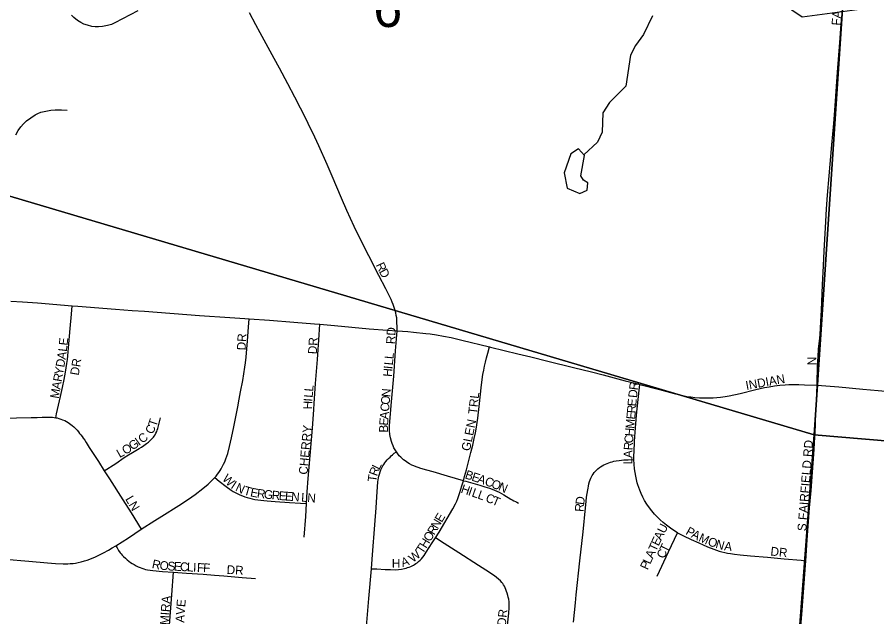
# Model space of a CAD drawing. Extents: x 1410790 to 1770854, y 448063 to 770588.
# Drawn here: x 1523216 to 1528108, y 619468 to 622880 of the extents above; entities that cross this region are included whole.
import ezdxf

# ---------------------------------------------------------------- set-up
doc = ezdxf.new("R2010")
doc.units = 0
for name, color, linetype in [('GM_X_City_Street', 7, 'Continuous'), ('GM_X_City_Street_Text', 7, 'Continuous'), ('GM_X_Minor_Lake', 7, 'Continuous'), ('GM_X_Minor_River', 7, 'Continuous'), ('GM_X_Section', 7, 'Continuous'), ('GM_X_Section_Text', 7, 'Continuous')]:
    doc.layers.add(name, color=color, linetype=linetype)

msp = doc.modelspace()

# ---------------------------------------------------------------- linework, layer by layer
at = {"layer": 'GM_X_City_Street'}
for points in [[(1527791.3, 621181.8), (1527793.1, 621212), (1527799.6, 621357.4), (1527804, 621464.9), (1527808.7, 621550.1), (1527815.7, 621681.1), (1527821.3, 621788.8), (1527826.5, 621867), (1527836.3, 621978.2), (1527852.7, 622154), (1527862.8, 622274.8), (1527868.3, 622350), (1527885.1, 622567.1), (1527897.2, 622735.6), (1527905.6, 622840.2), (1527915.8, 622957.8), (1527927.1, 623088.4), (1527939, 623232.3), (1527940.7, 623251.7)], [(1523902.7, 622916.6), (1523772.6, 622847.7), (1523752, 622839), (1523730.4, 622832.7), (1523701.9, 622827.5), (1523679.5, 622825.3), (1523660.4, 622825.5), (1523641.5, 622827.8), (1523616.5, 622834), (1523595.3, 622841.3), (1523578.2, 622849.7), (1523559.3, 622861.9), (1523538.9, 622877.7), (1523525.1, 622890.9)], [(1525379, 621095.1), (1525378.3, 621116), (1525377.5, 621144.7), (1525377.1, 621156.9), (1525375.8, 621169), (1525373.6, 621182.9), (1525370.1, 621198.1), (1525366.6, 621211.1), (1525362.7, 621223.3), (1525359.3, 621234.6), (1525355.3, 621245.4), (1525350.2, 621259.3), (1525344.1, 621273.2), (1525313.7, 621334.4), (1525274.2, 621409.9), (1525216.8, 621522.8), (1525184.8, 621585.7), (1525133.1, 621690), (1525091.5, 621779.3), (1525061.1, 621850.9), (1525008.1, 621975.4), (1524979.5, 622042.3), (1524932.6, 622147.7), (1524909.6, 622197.2), (1524871.8, 622275.7), (1524848.6, 622323.1), (1524828.4, 622363), (1524796.3, 622425.5), (1524756.4, 622500.2), (1524709, 622589.5), (1524679.4, 622644.4), (1524655.8, 622687.5), (1524598.8, 622790.9), (1524574.5, 622837.4), (1524538.1, 622905.5)], [(1523208.4, 622211.7), (1523221.8, 622234.9), (1523237.3, 622256.6), (1523252.8, 622274.3), (1523270, 622290.2), (1523293.9, 622308.2), (1523319, 622324.4), (1523334, 622332.3), (1523351.6, 622339), (1523369.1, 622343.8), (1523388.5, 622348), (1523408.3, 622351.4), (1523431.6, 622353.2), (1523449.2, 622353.9), (1523468, 622353.3), (1523501, 622351.2)], [(1523180.1, 621264.8), (1523246.7, 621261), (1523331.8, 621254.4), (1523529.2, 621237.9)], [(1523435.6, 620601), (1523440.4, 620622.5), (1523462.6, 620721.9), (1523473.8, 620773.3), (1523483.2, 620818.1), (1523491.5, 620860.4), (1523495.8, 620884.9), (1523499.5, 620909.2), (1523502.3, 620931.4), (1523504.5, 620952.2), (1523509.1, 620997.7), (1523518.1, 621109.2), (1523525.1, 621191), (1523529.2, 621237.9)], [(1523529.2, 621237.9), (1523560.6, 621235.3), (1523776.4, 621219.2), (1523871.2, 621211.7), (1523939.9, 621206.5), (1524253.8, 621183.2), (1524427.1, 621170.9), (1524512.2, 621165), (1524535.7, 621163.4)], [(1524340.5, 620260.3), (1524347.8, 620268.7), (1524356.3, 620279.6), (1524364.1, 620289.8), (1524370.4, 620299.6), (1524376.6, 620309.6), (1524383.4, 620322.3), (1524390.2, 620336.2), (1524396.9, 620350.3), (1524403.4, 620366.7), (1524408.6, 620381.3), (1524414.1, 620398), (1524424.5, 620436.3), (1524436, 620487), (1524449.4, 620548.2), (1524459.3, 620596), (1524471.5, 620662.9), (1524479.5, 620707.3), (1524487.8, 620748.8), (1524500.1, 620813.2), (1524506.7, 620851.4), (1524512.5, 620887.8), (1524515.4, 620912.5), (1524518.9, 620945.5), (1524527.1, 621038), (1524532.5, 621116.6), (1524535.7, 621163.4)], [(1524535.7, 621163.4), (1524652.9, 621155.5), (1524790.4, 621145.5), (1524908.1, 621135.7), (1524939, 621132.9)], [(1527769, 620786.5), (1527771.2, 620901.6), (1527773.4, 620948.3), (1527776.7, 620992), (1527781, 621035.8), (1527784.9, 621073.6), (1527791.3, 621181.8)], [(1524863.3, 620112.7), (1524866.9, 620179.4), (1524872.3, 620254.4), (1524877.6, 620319.2), (1524895.8, 620541.2), (1524902.2, 620619.3), (1524904.1, 620648.1), (1524905.9, 620682.7), (1524913.9, 620795.3), (1524925.2, 620932.3), (1524934.9, 621072.9), (1524939, 621132.9)], [(1524939, 621132.9), (1525022.5, 621125.4), (1525219.2, 621107), (1525323.9, 621098.9), (1525379, 621095.1)], [(1525373.9, 620407.6), (1525367, 620418.6), (1525360.4, 620430.3), (1525355.5, 620440.4), (1525350.3, 620453.7), (1525346.2, 620465.7), (1525340.1, 620487.3), (1525336.7, 620506.1), (1525335.1, 620528.5), (1525335, 620542.6), (1525335.8, 620557.5), (1525346.2, 620691.5), (1525359.1, 620837.6), (1525368.2, 620981.2), (1525379, 621095.1)], [(1525379, 621095.1), (1525440, 621090.9), (1525471.6, 621088.3), (1525541.9, 621081), (1525565.9, 621078.2), (1525601.7, 621073), (1525642.3, 621065.9), (1525685.2, 621056.5), (1525746.1, 621041.4), (1525904.6, 621003.8)], [(1525755.2, 620242.6), (1525762, 620266.2), (1525772.5, 620304.1), (1525798.1, 620402.6), (1525808.7, 620445), (1525817.3, 620482.4), (1525823.5, 620514.4), (1525829.6, 620546.9), (1525833.9, 620573.5), (1525837.4, 620598.8), (1525844.6, 620663.9), (1525857.8, 620787.9), (1525866.6, 620846.3), (1525870.8, 620872), (1525875, 620893.5), (1525881.1, 620917.9), (1525887.3, 620942.4), (1525894.4, 620967.6), (1525904.6, 621003.8)], [(1525904.6, 621003.8), (1525910, 621002.5), (1526065.9, 620964.5), (1526139.8, 620946.7), (1526235.3, 620922.8), (1526381.8, 620886.2), (1526483.8, 620861.1), (1526550.7, 620844), (1526676.8, 620811.7), (1526733.4, 620797.1), (1526758.9, 620790.3)], [(1526726.2, 620364), (1526726.1, 620385.4), (1526726.8, 620407), (1526730, 620466.2), (1526733.1, 620517.9), (1526741, 620615.2), (1526755.6, 620758.6), (1526758.9, 620790.3)], [(1526758.9, 620790.3), (1526871.1, 620760.7), (1526954.6, 620738.6), (1527004.6, 620726.9), (1527027, 620722.3), (1527049.2, 620719), (1527072.3, 620716.1), (1527099.6, 620714.2), (1527137.5, 620713.2), (1527176.5, 620713.9), (1527198.2, 620715.2), (1527218.8, 620717.2), (1527245.6, 620721.1), (1527266.9, 620724.9), (1527330.6, 620739.5), (1527419.9, 620761.8), (1527468.3, 620771.9), (1527495.6, 620777.2), (1527526.3, 620782), (1527557, 620785.7), (1527586, 620787.8), (1527607.9, 620789), (1527634.3, 620789.5), (1527665, 620789), (1527696.1, 620788.1), (1527769, 620786.5)], [(1527703.9, 619787), (1527712.4, 619905.2), (1527725.7, 620088.1), (1527733.8, 620186.1), (1527741.6, 620290.6), (1527747.2, 620367.3), (1527750.7, 620421.7), (1527755.6, 620490.3), (1527759.6, 620555.9), (1527761.6, 620643.9), (1527765, 620698.1), (1527769, 620786.5)], [(1527769, 620786.5), (1527891, 620777), (1528028.3, 620763.8), (1528116.4, 620755.2), (1528367.9, 620732.6), (1528652.3, 620707.5), (1528802.6, 620693.4), (1528926.5, 620682.1), (1529092.9, 620667.4), (1529174.6, 620659.2), (1529223.7, 620653), (1529246.8, 620649.2), (1529272.6, 620643.8), (1529299.7, 620636.9), (1529318.5, 620631.2), (1529340.7, 620623.7), (1529379.6, 620607), (1529415.4, 620589.2), (1529455.6, 620565.8), (1529480.5, 620549.3), (1529513, 620526.2), (1529586.1, 620470.5), (1529590.5, 620467.5)], [(1522432.1, 620598.7), (1522455.5, 620596.7), (1522569.6, 620587.1), (1522625.2, 620582.6), (1522641.5, 620581.3), (1522673.7, 620579.9), (1522752.2, 620579.9), (1522801.4, 620580.7), (1522893.1, 620585.4), (1522935.6, 620587.4), (1523017.3, 620591.3), (1523072.8, 620594.3), (1523134.5, 620596.4), (1523213, 620599.6), (1523295.2, 620601.4), (1523330.2, 620602.6), (1523358.4, 620604), (1523376.7, 620604.8), (1523393.6, 620604.5), (1523409.1, 620603.8), (1523417.3, 620603.4), (1523426.6, 620602.3), (1523435.6, 620601)], [(1523435.6, 620601), (1523444.4, 620599.3), (1523453.3, 620597.2), (1523464.3, 620593.4), (1523474.4, 620589.5), (1523486.5, 620584.1), (1523497.6, 620578.4), (1523506, 620573.9), (1523513.9, 620568.4), (1523521.4, 620563.1), (1523529.2, 620556.8), (1523538.8, 620548.5), (1523548.1, 620539.3), (1523556.6, 620530.1), (1523565.2, 620520.1), (1523571.6, 620512), (1523578.3, 620503.1), (1523585.4, 620493.8), (1523592.5, 620483.6), (1523600.2, 620472.8), (1523608.7, 620460.1), (1523626.6, 620431.7), (1523678.3, 620352), (1523711.5, 620297.7)], [(1523711.5, 620297.7), (1523776.8, 620341), (1523825.6, 620374.4), (1523849.2, 620389), (1523873.1, 620403.6), (1523910.3, 620424.8), (1523924.1, 620433.5), (1523937.8, 620442.8), (1523951.6, 620453.2), (1523964, 620462.6), (1523973.1, 620470.3), (1523981.1, 620478), (1523986.8, 620483.8), (1523992, 620490.4), (1523996.6, 620496.6), (1524001.2, 620504), (1524005.7, 620512.4), (1524010, 620521.6), (1524013.7, 620530.7), (1524016.9, 620540), (1524026.9, 620578), (1524032.5, 620600.4)], [(1525232.3, 619741.6), (1525232.3, 619742), (1525238, 619820.6), (1525251.1, 619990.7), (1525258.2, 620088.9), (1525262.5, 620151), (1525269.3, 620235.9), (1525270.8, 620247), (1525272.4, 620258.2), (1525274.7, 620268.9), (1525277.8, 620280), (1525282.1, 620292.5), (1525286.4, 620304.2), (1525291.8, 620316.2), (1525297.7, 620327.2), (1525302.2, 620334.8), (1525308, 620343.4), (1525314.8, 620352.2), (1525322.2, 620360.8), (1525330, 620369.4), (1525337.9, 620377.1), (1525344.6, 620383.5), (1525352.2, 620390.2), (1525362.2, 620398.3), (1525373.9, 620407.6)], [(1525755.2, 620242.6), (1525664.5, 620268.9), (1525582.8, 620292.7), (1525546.9, 620302.6), (1525513.5, 620312.3), (1525498.5, 620316.9), (1525485.8, 620321.3), (1525473.1, 620326.3), (1525462.1, 620331.3), (1525449.4, 620338), (1525439.7, 620343.8), (1525431.7, 620349.1), (1525423.9, 620354.6), (1525414.9, 620361.8), (1525406.6, 620369), (1525398.5, 620377), (1525390.8, 620384.8), (1525381.9, 620395.7), (1525373.9, 620407.6)], [(1526382, 619437.4), (1526392.5, 619548), (1526396.6, 619593.6), (1526417.1, 619785.7), (1526425.5, 619853.4), (1526434.6, 619934.1), (1526440.8, 619988.7), (1526446.4, 620050.6), (1526453.8, 620124.7), (1526456.9, 620147.9), (1526460.1, 620169.9), (1526463.4, 620190.1), (1526465.3, 620200.6), (1526467.3, 620212.2), (1526470, 620224.9), (1526473.6, 620238.2), (1526476.5, 620247.4), (1526480.3, 620257.3), (1526483.9, 620264.6), (1526488.3, 620272.4), (1526493.5, 620280.2), (1526500.2, 620289), (1526506.3, 620296.1), (1526514, 620303.8), (1526521, 620310.4), (1526529.3, 620317.1), (1526536, 620321.5), (1526544.5, 620326.5), (1526555.1, 620332.1), (1526564, 620336.3), (1526573.8, 620340.7), (1526582.6, 620344.1), (1526592.6, 620347.6), (1526602.2, 620350.3), (1526612.1, 620352.7), (1526625.6, 620355.1), (1526641.7, 620357.3), (1526668.8, 620360.3), (1526693.3, 620362), (1526726.2, 620364)], [(1526974.3, 619945.9), (1526953.2, 619958.7), (1526933.1, 619972.6), (1526910.9, 619989.9), (1526892.8, 620004.1), (1526875, 620019.5), (1526857.9, 620036.3), (1526843.5, 620052), (1526820.8, 620079.6), (1526800, 620108.6), (1526786.4, 620130.4), (1526776.9, 620148.9), (1526767.1, 620168.9), (1526759.3, 620187.9), (1526753.6, 620203.1), (1526748.5, 620218.2), (1526744.8, 620230.7), (1526740.5, 620248.5), (1526736.4, 620268.6), (1526732.9, 620288.3), (1526729.5, 620310.3), (1526727.2, 620335.8), (1526726.2, 620364)], [(1523711.5, 620297.7), (1523740.6, 620252.3), (1523816.6, 620134), (1523863.9, 620059.3), (1523922.3, 619965.8)], [(1523922.3, 619965.8), (1524000.3, 620015.8), (1524039.2, 620040.1), (1524136.5, 620101.4), (1524190.8, 620138.1), (1524228.6, 620164.5), (1524273.4, 620198.1), (1524303.8, 620223.6), (1524327.8, 620246.6), (1524340.5, 620260.3)], [(1524340.5, 620260.3), (1524365.7, 620240.2), (1524404.5, 620209.9), (1524434, 620188.8), (1524445.6, 620181.5), (1524456.9, 620175.1), (1524471, 620167.8), (1524483.7, 620162), (1524497.6, 620156.5), (1524511.6, 620151.4), (1524525.1, 620147), (1524540.2, 620142.9), (1524553.8, 620139.3), (1524569.3, 620136.3), (1524585.1, 620133.9), (1524602.1, 620132), (1524620.4, 620130), (1524639.5, 620128.4), (1524661, 620126.5), (1524684.7, 620124.9), (1524765.5, 620118.9), (1524827.7, 620115), (1524863.3, 620112.7)], [(1525596.1, 619917.4), (1525616.6, 619949.2), (1525696.2, 620081.4), (1525711, 620110.6), (1525717.9, 620126.1), (1525723.8, 620140.8), (1525729.9, 620157.4), (1525735.5, 620174.8), (1525746.5, 620212.6), (1525755.2, 620242.6)], [(1525755.2, 620242.6), (1525768.7, 620238.9), (1525848.1, 620216.6), (1525877.2, 620208), (1525904.8, 620199.3), (1525919.5, 620194.3), (1525932.9, 620189.3), (1525946.2, 620183.5), (1525959.8, 620176.7), (1525972.4, 620170), (1525985.9, 620162.3), (1526024.5, 620137.5), (1526033, 620132.7), (1526041.5, 620128.4), (1526051.4, 620123.6), (1526060.3, 620119.4), (1526069.7, 620115.5)], [(1524849.5, 619921.6), (1524858.9, 620038.8), (1524863.3, 620112.7)], [(1523777.7, 619871.6), (1523848.9, 619917.7), (1523922.3, 619965.8)], [(1526858.1, 619698.2), (1526922.1, 619836.7), (1526974.3, 619945.9)], [(1526974.3, 619945.9), (1527008.3, 619928.7), (1527051.6, 619908.5), (1527095.9, 619888), (1527144.7, 619866.8), (1527180.9, 619852.4), (1527211.5, 619841.8), (1527226.7, 619837.2), (1527242.9, 619833.4), (1527258.3, 619830.1), (1527274.8, 619827.3), (1527299, 619823.6), (1527329.7, 619820.1), (1527389.5, 619814.4), (1527486.9, 619806.8), (1527581, 619798.1), (1527677.4, 619789.4), (1527703.9, 619787)], [(1525232.3, 619741.6), (1525262, 619740.4), (1525310.6, 619738), (1525341.1, 619736.6), (1525367.5, 619736.1), (1525386.6, 619737.1), (1525402.9, 619739.3), (1525419.5, 619742.7), (1525428.8, 619745.3), (1525438, 619748.3), (1525446.4, 619750.9), (1525456.4, 619754.8), (1525463.2, 619757.6), (1525471.3, 619761.7), (1525477.9, 619765.9), (1525485.1, 619770.5), (1525492.7, 619775.8), (1525500.7, 619782.6), (1525508.7, 619789.9), (1525517.1, 619798.7), (1525524.1, 619807.3), (1525531.4, 619816.8), (1525544.5, 619835.6), (1525577.5, 619888.5), (1525596.1, 619917.4)], [(1525994.4, 619316.3), (1526013.2, 619489), (1526015.8, 619518.5), (1526016.4, 619527.7), (1526016, 619538.1), (1526015.2, 619552.8), (1526013.2, 619567.5), (1526010.9, 619579.4), (1526008.5, 619589.9), (1526005.1, 619602.2), (1526001.5, 619612.6), (1525997.2, 619623.4), (1525992.8, 619633.1), (1525988.5, 619641.9), (1525983.3, 619650.4), (1525979, 619656.9), (1525973.8, 619663.7), (1525965.7, 619672.5), (1525955.1, 619682.1), (1525944.4, 619690.9), (1525932, 619700.4), (1525883.6, 619734.1), (1525842.2, 619760.6), (1525728.8, 619832.8), (1525645.7, 619885.2), (1525596.1, 619917.4)], [(1523147.5, 619795.4), (1523281.6, 619785.2), (1523389.3, 619775.1), (1523434, 619772), (1523477.9, 619769.5), (1523491.5, 619769.2), (1523504.4, 619769.4), (1523518.6, 619770.3), (1523534.3, 619772), (1523547.9, 619774), (1523563.7, 619777), (1523580.9, 619781.1), (1523599.1, 619785.9), (1523614.8, 619790.5), (1523629.8, 619795.4), (1523643.6, 619801.3), (1523658.1, 619807.7), (1523681.2, 619818.4), (1523708.3, 619832.7), (1523735.2, 619847), (1523756.9, 619859.5), (1523777.7, 619871.6)], [(1523777.7, 619871.6), (1523781.2, 619865.4), (1523784.5, 619859.5), (1523788.8, 619851.9), (1523793.6, 619844.6), (1523802.3, 619832.8), (1523808, 619825.9), (1523814.2, 619819.4), (1523822.1, 619810.4), (1523832, 619800.8), (1523841.2, 619792.7), (1523851.7, 619784.3), (1523861, 619777.7), (1523870.1, 619771.4), (1523881, 619764.9), (1523892.4, 619758.6), (1523904, 619752.9), (1523915.8, 619747.8), (1523925.9, 619743.8), (1523936.9, 619740.2), (1523947.1, 619737.5), (1523958.7, 619735.1), (1523972.8, 619733), (1523987.5, 619731.1), (1524042.7, 619726.3), (1524105.3, 619721.1)], [(1525142.1, 618661.5), (1525147.9, 618731.8), (1525159.3, 618869.2), (1525173, 619042.5), (1525185.1, 619179.9), (1525196.2, 619317.2), (1525202.4, 619389.1), (1525217.3, 619572.2), (1525232.3, 619741.6)], [(1527669.6, 619344.3), (1527682.8, 619505.5), (1527702, 619761.3), (1527703.9, 619787)], [(1524078.3, 619332.6), (1524083.5, 619420.2), (1524096.7, 619592.5), (1524105.3, 619721.1)], [(1524105.3, 619721.1), (1524106, 619721.1), (1524179.9, 619716.6), (1524274.6, 619710.2), (1524339.9, 619705.5), (1524392.2, 619701.5), (1524497.3, 619692.1), (1524571.6, 619686.7)]]:
    msp.add_lwpolyline(points, dxfattribs=at)
at = {"layer": 'GM_X_Minor_Lake'}
for points in [[(1526444.3, 622092.7), (1526411, 622131.5), (1526366.4, 622102.4), (1526328.3, 621994.9), (1526346.6, 621908.2), (1526418.1, 621876.5), (1526460.6, 621895.6), (1526463.4, 621937.7), (1526439.6, 621952.3), (1526424, 621976.7)], [(1526424, 621976.7), (1526444.3, 622092.7)]]:
    msp.add_lwpolyline(points, dxfattribs=at)
at = {"layer": 'GM_X_Minor_River'}
for points in [[(1527996.4, 622921.4), (1527683.1, 622880.1), (1527566.5, 622960.9)], [(1526832, 622888.8), (1526779.9, 622781.6), (1526734.7, 622718.3), (1526705.6, 622664.8), (1526680.1, 622486.8), (1526586.3, 622394.5), (1526549.1, 622335.2), (1526545, 622226.9)], [(1526545, 622226.9), (1526517.9, 622169.3), (1526439.9, 622097.7)]]:
    msp.add_lwpolyline(points, dxfattribs=at)
at = {"layer": 'GM_X_Section'}
for points in [[(1522801.4, 625129.5), (1527484, 624666.3), (1528025, 624614.9), (1527751.7, 620502.8), (1522551.9, 622046.6)], [(1528025, 624614.9), (1532828.2, 624183.7), (1533518.9, 624117.7), (1533190.3, 620044.5), (1527751.7, 620502.8)], [(1527751.7, 620502.8), (1527349.3, 615167.2), (1522119.9, 616619.5), (1522551.9, 622046.6)], [(1533190.3, 620044.5), (1532724.4, 614740.1), (1527349.3, 615167.2), (1527751.7, 620502.8)]]:
    msp.add_lwpolyline(points, close=True, dxfattribs=at)

# ---------------------------------------------------------------- texts
at = {"layer": 'GM_X_City_Street_Text'}
for s, rotation, p in [('FAIRFIELD', 85.169, (1527899.9, 622831.2)), ('R', 295.1856, (1525255.7, 621470.6)), ('D', 297.6797, (1525273.5, 621432.7)), ('RD', 86.8222, (1525365.3, 621018.5)), ('DR', 86.989, (1524516.1, 620983.3)), ('E', 83.6575, (1523502.3, 621010)), ('DR', 86.989, (1524920.9, 620961.3)), ('A', 81.3306, (1523491.3, 620929.4)), ('L', 83.2943, (1523498.1, 620974.7)), ('L', 84.4695, (1525356.8, 620932.7)), ('D', 79.9949, (1523483.4, 620884.8)), ('DR', 81.028, (1523566.3, 620839.2)), ('L', 84.4716, (1525353.5, 620897.6)), ('N', 90, (1527763.5, 620899.2)), ('Y', 79.9806, (1523475.8, 620841.5)), ('H', 85.142, (1525347.6, 620832.1)), ('I', 84.5286, (1525351.4, 620875.8)), ('R', 79.9906, (1523468.9, 620802.5)), ('INDIAN', 10.4039, (1527366.2, 620758.7)), ('A', 79.9844, (1523461.2, 620759.1)), ('L', 85.0888, (1524900, 620748.3)), ('R', 82.167, (1526746.9, 620755.3)), ('M', 79.9867, (1523452, 620707.1)), ('L', 85.4043, (1524897.2, 620713.2)), ('O', 85.3289, (1525335.2, 620673.3)), ('N', 85.336, (1525338.8, 620717.2)), ('TRL', 83.4219, (1525831.7, 620618.6)), ('D', 84.583, (1526742.9, 620712)), ('H', 88.5575, (1524894.5, 620648)), ('I', 85.7773, (1524895.6, 620691.4)), ('C', 85.3433, (1525332, 620633.9)), ('R', 84.9782, (1526735.2, 620624.4)), ('E', 84.993, (1526738.6, 620663.9)), ('A', 85.3725, (1525328.5, 620590)), ('E', 84.98, (1526732.1, 620589.4)), ('T', 71.3776, (1524006.8, 620545.4)), ('E', 86.3504, (1525326.2, 620555.1)), ('GLEN', 78.4074, (1525792.2, 620408.1)), ('M', 84.9853, (1526727.5, 620536.8)), ('C', 63.1462, (1523985.9, 620502.8)), ('CHERRY', 84.8987, (1524868.1, 620275.2)), ('B', 89.15, (1525325.7, 620516.2)), ('H', 84.9768, (1526723.6, 620492.9)), ('G', 35.2931, (1523872.5, 620413.2)), ('I', 36.3272, (1523909.3, 620439.2)), ('C', 36.3308, (1523927, 620452.2)), ('C', 84.9903, (1526720.2, 620453.5)), ('O', 30.42, (1523830.7, 620388.4)), ('R', 85.5994, (1526717.1, 620414.2)), ('S FAIRFIELD RD', 85.6416, (1527706.1, 619953.9)), ('L', 29.4805, (1523799.3, 620370.6)), ('A', 88.6668, (1526716.1, 620370.9)), ('L', 63.6915, (1525276.5, 620301)), ('L', 89.877, (1526716.1, 620335.9)), ('W', 315.7311, (1524379.3, 620249)), ('R', 69.8333, (1525263.4, 620265.1)), ('B', 341.542, (1525760.4, 620256.9)), ('E', 341.5132, (1525798, 620244.4)), ('I', 326.3961, (1524428.1, 620202.7)), ('T', 82.6175, (1525259.6, 620233.1)), ('A', 341.5289, (1525831.4, 620233.2)), ('C', 340.5398, (1525872.9, 620219.3)), ('O', 337.6954, (1525909.6, 620206.4)), ('N', 336.6522, (1525950.1, 620189.8)), ('N', 335.0874, (1524453.7, 620186.5)), ('T', 343.9831, (1524501.5, 620165)), ('E', 348.5988, (1524539.6, 620154.2)), ('R', 353.1411, (1524578.4, 620146.6)), ('G', 353.4975, (1524618.1, 620141.8)), ('R', 354.5886, (1524662.8, 620136.7)), ('E', 355.8162, (1524703.4, 620132.9)), ('H', 341.0328, (1525737, 620175.5)), ('I', 340.9915, (1525778.6, 620161.2)), ('L', 340.7615, (1525799.3, 620154.1)), ('L', 340.2433, (1525832.4, 620142.5)), ('LN', 300.4686, (1523829.6, 620138.3)), ('E', 355.9118, (1524738.6, 620130.3)), ('N', 355.9097, (1524773.7, 620127.8)), ('L', 355.9189, (1524830.8, 620123.7)), ('N', 355.9165, (1524865.9, 620121.2)), ('C', 337.4726, (1525877.3, 620126.2)), ('T', 336.9198, (1525913.8, 620111.1)), ('D', 82.8235, (1526442, 620102.6)), ('R', 85.4299, (1526438.9, 620063.7)), ('E', 59.2035, (1525632.1, 620001.2)), ('R', 59.207, (1525589.3, 619929.4)), ('N', 59.1993, (1525609.5, 619963.4)), ('U', 63.4349, (1526900.5, 619938.4)), ('O', 59.2149, (1525566.7, 619891.6)), ('A', 63.4349, (1526880.8, 619899)), ('P', 331.1802, (1527016.1, 619939.4)), ('A', 332.8682, (1527048.3, 619921.7)), ('M', 335.3936, (1527089.7, 619900.5)), ('H', 59.0815, (1525544.1, 619853.7)), ('T', 65.4501, (1526851.2, 619835.6)), ('E', 64.5226, (1526865.8, 619867.5)), ('T', 64.2659, (1526913.9, 619830.7)), ('O', 340.19, (1527141.9, 619876.8)), ('N', 343.9383, (1527186.7, 619860.8)), ('A', 352.9492, (1527237.4, 619846.9)), ('W', 39.3772, (1525468.2, 619773.9)), ('T', 56.5211, (1525523.3, 619822.3)), ('A', 65.4394, (1526832.9, 619795.6)), ('C', 65.4123, (1526897.6, 619794.9)), ('DR', 353.6511, (1527500.9, 619817.3)), ('R', 347.89, (1523979.9, 619746.1)), ('H', 0.4371, (1525348.4, 619747)), ('A', 18.8583, (1525409.6, 619750.3)), ('L', 65.4501, (1526818.3, 619763.6)), ('O', 354.5803, (1524024.9, 619736.8)), ('S', 356.8605, (1524070.9, 619732.5)), ('E', 357.2005, (1524106.3, 619730.6)), ('C', 357.1819, (1524141.5, 619728.9)), ('L', 357.1827, (1524181, 619726.9)), ('I', 357.1952, (1524216.2, 619725.2)), ('F', 357.1847, (1524238.2, 619724.1)), ('F', 357.1897, (1524273.3, 619722.4)), ('DR', 356.9887, (1524407.2, 619711.7)), ('P', 65.4396, (1526803.7, 619731.6)), ('ALMIRA', 85.8387, (1524071.7, 619337.9)), ('AVE', 86.0531, (1524166.3, 619433.1)), ('CAMBRIA DR', 84.1597, (1525963.7, 619091.6))]:
    msp.add_text(s, height=50, rotation=rotation, dxfattribs=at).set_placement(p)
at = {"layer": 'GM_X_Section_Text'}
msp.add_text('6', height=221, rotation=0, dxfattribs=at).set_placement((1525242.7, 622824.5))

doc.saveas('drawing.dxf')
